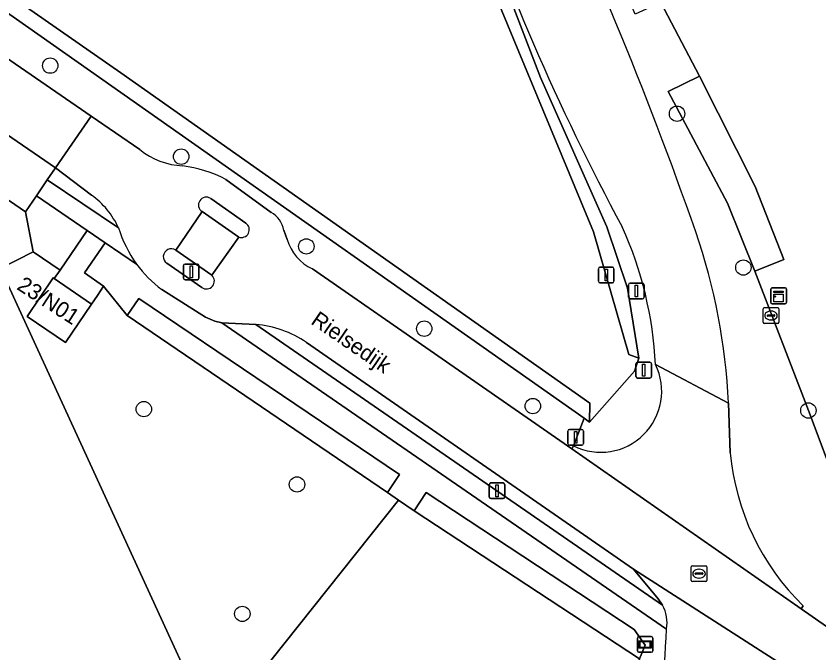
# Model space of a CAD drawing. Extents: x 163859 to 164644, y 379566 to 382155.
# Drawn here: x 164405.8 to 164456.9, y 381680.8 to 381721.3 of the extents above; entities that cross this region are included whole.
import ezdxf

# ---------------------------------------------------------------- set-up
doc = ezdxf.new("R2010")
doc.units = 0
for name, color, linetype in [('IMGEO_Afsluitpaal', 7, 'Continuous'), ('IMGEO_Boom', 7, 'Continuous'), ('IMGEO_Erf', 7, 'Continuous'), ('IMGEO_Groenvoorziening', 7, 'Continuous'), ('IMGEO_Haag', 7, 'Continuous'), ('IMGEO_Hek', 7, 'Continuous'), ('IMGEO_Kast', 7, 'Continuous'), ('IMGEO_Lichtmast', 7, 'Continuous'), ('IMGEO_Openbare_ruimte_label', 7, 'Continuous'), ('IMGEO_Pand', 7, 'Continuous'), ('IMGEO_Pand_nummerreeks', 7, 'Continuous'), ('IMGEO_Parkeervlak_open', 7, 'Continuous'), ('IMGEO_Rijbaan_lokaal_gesloten', 7, 'Continuous'), ('IMGEO_Rijbaan_lokaal_halfverhard', 7, 'Continuous'), ('IMGEO_Rijbaan_lokaal_open', 7, 'Continuous'), ('IMGEO_Rioolput', 7, 'Continuous'), ('IMGEO_Verkeersbordpaal', 7, 'Continuous'), ('IMGEO_Voetpad_open', 7, 'Continuous'), ('IMGEO_Waterloop', 7, 'Continuous'), ('IMGEO_Wegwijzer', 7, 'Continuous')]:
    doc.layers.add(name, color=color, linetype=linetype)

msp = doc.modelspace()

# ---------------------------------------------------------------- linework, layer by layer
at = {"layer": 'IMGEO_Afsluitpaal'}
for p, q in [((164444.797, 381703.434), (164444.797, 381704.234)), ((164444.797, 381704.234), (164444.797, 381703.434)), ((164444.897, 381704.334), (164445.687, 381704.334)), ((164445.687, 381704.334), (164444.897, 381704.334)), ((164445.787, 381704.234), (164445.787, 381703.434)), ((164445.787, 381703.434), (164445.787, 381704.234)), ((164445.687, 381703.334), (164444.897, 381703.334)), ((164444.897, 381703.334), (164445.687, 381703.334)), ((164445.274, 381698.398), (164445.274, 381699.198)), ((164445.274, 381699.198), (164445.274, 381698.398)), ((164445.374, 381699.298), (164446.164, 381699.298)), ((164446.164, 381699.298), (164445.374, 381699.298)), ((164446.264, 381699.198), (164446.264, 381698.398)), ((164446.264, 381698.398), (164446.264, 381699.198)), ((164446.164, 381698.298), (164445.374, 381698.298)), ((164445.374, 381698.298), (164446.164, 381698.298)), ((164440.936, 381694.125), (164440.936, 381694.925)), ((164440.936, 381694.925), (164440.936, 381694.125)), ((164441.036, 381695.025), (164441.826, 381695.025)), ((164441.826, 381695.025), (164441.036, 381695.025)), ((164441.926, 381694.925), (164441.926, 381694.125)), ((164441.926, 381694.125), (164441.926, 381694.925)), ((164441.826, 381694.025), (164441.036, 381694.025)), ((164441.036, 381694.025), (164441.826, 381694.025))]:
    msp.add_line(p, q, dxfattribs=at)
for points in [[(164445.217, 381704.209), (164445.367, 381704.209), (164445.367, 381703.459), (164445.217, 381703.459), (164445.217, 381704.209)], [(164445.694, 381699.173), (164445.844, 381699.173), (164445.844, 381698.423), (164445.694, 381698.423), (164445.694, 381699.173)], [(164441.356, 381694.9), (164441.506, 381694.9), (164441.506, 381694.15), (164441.356, 381694.15), (164441.356, 381694.9)]]:
    msp.add_lwpolyline(points, dxfattribs=at)
for centre, start, end in [((164444.897, 381704.234), 90, 180), ((164444.897, 381704.234), 90, 180), ((164445.687, 381704.234), 0, 90), ((164445.687, 381704.234), 360, 90), ((164444.897, 381703.434), 180, 270), ((164444.897, 381703.434), 180, 270), ((164445.687, 381703.434), 270, 0), ((164445.687, 381703.434), 270, 0), ((164445.374, 381699.198), 90, 180), ((164445.374, 381699.198), 90, 180), ((164446.164, 381699.198), 0, 90), ((164446.164, 381699.198), 360, 90), ((164445.374, 381698.398), 180, 270), ((164445.374, 381698.398), 180, 270), ((164446.164, 381698.398), 270, 0), ((164446.164, 381698.398), 270, 0), ((164441.036, 381694.925), 90, 180), ((164441.036, 381694.925), 90, 180), ((164441.826, 381694.925), 0, 90), ((164441.826, 381694.925), 360, 90), ((164441.036, 381694.125), 180, 270), ((164441.036, 381694.125), 180, 270), ((164441.826, 381694.125), 270, 0), ((164441.826, 381694.125), 270, 0)]:
    msp.add_arc(centre, 0.1, start, end, dxfattribs=at)
at = {"layer": 'IMGEO_Boom'}
for centre in [(164407.999, 381718.165), (164447.885, 381715.108), (164416.332, 381712.377), (164424.297, 381706.667), (164452.106, 381705.325), (164431.799, 381701.437), (164438.709, 381696.515), (164413.958, 381696.321), (164456.242, 381696.233), (164423.704, 381691.53), (164420.224, 381683.299)]:
    msp.add_circle(centre, 0.489, dxfattribs=at)
at = {"layer": 'IMGEO_Erf'}
for points in [[(164373.541, 381743.437), (164381.128, 381738.044), (164380.075, 381736.577), (164381.302, 381735.727), (164381.018, 381735.317), (164382.848, 381734.057), (164384.279, 381736.27), (164384.767, 381737.008), (164412.499, 381717.701), (164442.345, 381696.707), (164442.313, 381695.498), (164445.182, 381698.732), (164445.453, 381699.564), (164444.814, 381699.801), (164442.562, 381707.597), (164432.716, 381731.373), (164424.257, 381752.745), (164423.35, 381755.66), (164420.288, 381764.098), (164421.545, 381764.607), (164416.201, 381779.849)], [(164545.187, 381772.796), (164538.087, 381770.586), (164534.647, 381771.115), (164468.83, 381745.172), (164457.1, 381740.602), (164440.833, 381734.263), (164442.117, 381733.052), (164446.861, 381722.173), (164449.308, 381717.487), (164452.858, 381710.476), (164454.684, 381705.828), (164452.839, 381705.104), (164456.242, 381696.233), (164460.508, 381684.892), (164470.413, 381677.426)], [(164404.83, 381705.266), (164406.925, 381706.323), (164406.418, 381708.86), (164381.892, 381725.724), (164366.579, 381736.251)], [(164441.086, 381626.391), (164437.24, 381634.76), (164435.396, 381638.772), (164432.979, 381644.03), (164418.395, 381675.757), (164404.83, 381705.266)]]:
    msp.add_lwpolyline(points, dxfattribs=at)
at = {"layer": 'IMGEO_Groenvoorziening'}
for points in [[(164455.903, 381683.819), (164455.774, 381683.629), (164466.526, 381676.141), (164470.413, 381677.426), (164460.508, 381684.892), (164456.242, 381696.233), (164452.839, 381705.104), (164451.098, 381709.418), (164447.311, 381716.527), (164449.308, 381717.487), (164446.861, 381722.173), (164445.218, 381721.442), (164440.48, 381732.584), (164442.117, 381733.052), (164440.833, 381734.263), (164434.331, 381751.745), (164433.997, 381752.734), (164433.526, 381754.803), (164427.546, 381772.442), (164427.349, 381773.022), (164418.253, 381799.855)], [(164416.201, 381779.849), (164421.545, 381764.607), (164424.509, 381756.221), (164425.411, 381753.268), (164439.193, 381717.401), (164443.41, 381707.913), (164444.739, 381704.016), (164445.453, 381699.564), (164445.182, 381698.732), (164442.313, 381695.498), (164441.971, 381695.738), (164441.297, 381693.99)], [(164411.916, 381716.853), (164384.279, 381736.27), (164382.848, 381734.057), (164385.909, 381731.949), (164410.608, 381714.952), (164413.701, 381712.823)], [(164424.684, 381705.234), (164441.191, 381693.787), (164441.297, 381693.99), (164441.971, 381695.738), (164411.916, 381716.853)], [(164408.346, 381711.663), (164407.816, 381710.901)], [(164410.627, 381709.931), (164408.346, 381711.663)], [(164407.816, 381710.901), (164412.337, 381707.852)], [(164419.173, 381710.931), (164422.052, 381708.834)], [(164420.438, 381708.15), (164418.21, 381709.722)], [(164417.659, 381708.884), (164419.995, 381707.267)], [(164422.863, 381707.691), (164423.088, 381707.112)], [(164413.488, 381705.549), (164411.502, 381706.899), (164410.178, 381704.987), (164411.398, 381704.132), (164412.893, 381702.27), (164413.634, 381703.357), (164430.229, 381692.16), (164429.462, 381691.018), (164430.172, 381690.536), (164431.154, 381689.854), (164431.926, 381691.02), (164445.149, 381682.312), (164445.862, 381681.301), (164445.507, 381680.437), (164441.513, 381656.721), (164439.427, 381648.452), (164432.979, 381644.03), (164435.396, 381638.772), (164437.55, 381639.663), (164442.442, 381643.541)], [(164418.287, 381704.834), (164415.993, 381706.42)], [(164415.41, 381705.593), (164417.638, 381704.058)], [(164447.209, 381682.336), (164418.924, 381701.808), (164418.468, 381701.923), (164417.871, 381702.173), (164415.108, 381703.926)], [(164421.084, 381701.704), (164446.953, 381683.86), (164446.689, 381684.251), (164445.106, 381686.132), (164424.306, 381700.566)], [(164451.153, 381696.71), (164451.272, 381693.533)]]:
    msp.add_lwpolyline(points, dxfattribs=at)
for points in [[(164406.925, 381706.323), (164408.629, 381705.166), (164410.356, 381707.679), (164407.122, 381709.878), (164406.418, 381708.86)], [(164412.893, 381702.27), (164411.398, 381704.132), (164411.007, 381703.551), (164410.636, 381702.998), (164408.971, 381700.556), (164406.531, 381702.22), (164408.196, 381704.662), (164408.255, 381704.621), (164408.629, 381705.166), (164406.925, 381706.323), (164404.83, 381705.266), (164418.395, 381675.757), (164430.172, 381690.536), (164429.462, 381691.018)], [(164445.507, 381680.437), (164431.154, 381689.854), (164430.172, 381690.536), (164418.395, 381675.757), (164432.979, 381644.03), (164439.427, 381648.452), (164441.513, 381656.721)]]:
    msp.add_lwpolyline(points, close=True, dxfattribs=at)
for centre, radius, start, end in [((164221.983, 381628.478), 240.478, 19.20953, 25.99054), ((164576.493, 381779.107), 150.062, 198.44616, 208.32428), ((164416.629, 381716.454), 4.664, 231.1133, 267.4426), ((164415.29, 381703.367), 8.502, 62.8239, 82.3543), ((164407.619, 381705.714), 5.18, 24.3783, 54.497), ((164417.936, 381709.302), 0.501, 56.8492, 236.4995), ((164421.259, 381707.412), 1.628, 9.8569, 60.8573), ((164420.17, 381707.732), 0.497, 249.3569, 57.3574), ((164422.47, 381697.97), 24.074, 2.8147, 24.3816), ((164413.003, 381695.065), 38.185, 2.4692, 19.1656), ((164425.923, 381707.905), 2.944, 195.6158, 245.1027), ((164415.7, 381706.008), 0.506, 54.5679, 235.0676), ((164419.638, 381710.068), 7.632, 216.3064, 233.5876), ((164417.937, 381704.467), 0.507, 233.8282, 46.3576), ((164420.507, 381694.941), 6.788, 55.9678, 85.1261), ((164443.036, 381697.45), 3.873, 243.3112, 26.0706), ((164466.8, 381694.975), 15.595, 185.3051, 225.6724), ((164384.013, 381684.587), 63.236, 349.92525, 357.95994)]:
    msp.add_arc(centre, radius, start, end, dxfattribs=at)
at = {"layer": 'IMGEO_Haag'}
for points in [[(164408.346, 381711.663), (164407.816, 381710.901)], [(164410.627, 381709.931), (164408.346, 381711.663)], [(164407.816, 381710.901), (164412.337, 381707.852)], [(164420.438, 381708.15), (164418.21, 381709.722)], [(164417.659, 381708.884), (164419.995, 381707.267)], [(164418.287, 381704.834), (164415.993, 381706.42)], [(164415.41, 381705.593), (164417.638, 381704.058)], [(164421.084, 381701.704), (164446.953, 381683.86), (164446.689, 381684.251), (164445.106, 381686.132), (164424.306, 381700.566)]]:
    msp.add_lwpolyline(points, dxfattribs=at)
for centre, radius, start, end in [((164407.619, 381705.714), 5.18, 24.3783, 54.497), ((164417.936, 381709.302), 0.501, 56.8492, 236.4995), ((164420.17, 381707.732), 0.497, 249.3569, 57.3574), ((164415.7, 381706.008), 0.506, 54.5679, 235.0676), ((164417.937, 381704.467), 0.507, 233.8282, 46.3576), ((164420.507, 381694.941), 6.788, 55.9678, 85.1261)]:
    msp.add_arc(centre, radius, start, end, dxfattribs=at)
at = {"layer": 'IMGEO_Hek'}
for points in [[(164429.462, 381691.018), (164430.172, 381690.536)], [(164430.172, 381690.536), (164418.395, 381675.757)]]:
    msp.add_lwpolyline(points, dxfattribs=at)
at = {"layer": 'IMGEO_Kast'}
for p, q in [((164453.925, 381704.024), (164454.766, 381704.024)), ((164454.766, 381704.024), (164453.925, 381704.024)), ((164453.85, 381703.099), (164453.85, 381703.94)), ((164453.85, 381703.94), (164453.85, 381703.099)), ((164454.85, 381703.949), (164454.85, 381703.108)), ((164454.85, 381703.108), (164454.85, 381703.949)), ((164454.775, 381703.024), (164453.934, 381703.024)), ((164453.934, 381703.024), (164454.775, 381703.024))]:
    msp.add_line(p, q, dxfattribs=at)
for points in [[(164454.045, 381703.814), (164454.645, 381703.814), (164454.645, 381703.729), (164454.045, 381703.729), (164454.045, 381703.814)], [(164454.045, 381703.639), (164454.645, 381703.639), (164454.645, 381703.15), (164454.045, 381703.15), (164454.045, 381703.639)]]:
    msp.add_lwpolyline(points, dxfattribs=at)
msp.add_circle((164454.129, 381703.488), 0.0377, dxfattribs=at)
for centre, start, end in [((164453.928, 381703.946), 92.4484, 184.2845), ((164453.928, 381703.946), 92.4484, 184.2845), ((164454.772, 381703.946), 2.4484, 94.2845), ((164454.772, 381703.946), 2.4484, 94.2845), ((164453.928, 381703.102), 182.4484, 274.2845), ((164453.928, 381703.102), 182.4484, 274.2845), ((164454.772, 381703.102), 272.4484, 4.2845), ((164454.772, 381703.102), 272.4484, 4.2845)]:
    msp.add_arc(centre, 0.0779, start, end, dxfattribs=at)
at = {"layer": 'IMGEO_Lichtmast'}
for p, q in [((164416.477, 381704.649), (164416.477, 381705.449)), ((164416.477, 381705.449), (164416.477, 381704.649)), ((164416.577, 381705.549), (164417.367, 381705.549)), ((164417.367, 381705.549), (164416.577, 381705.549)), ((164417.467, 381705.449), (164417.467, 381704.649)), ((164417.467, 381704.649), (164417.467, 381705.449)), ((164417.367, 381704.549), (164416.577, 381704.549)), ((164416.577, 381704.549), (164417.367, 381704.549)), ((164435.935, 381690.728), (164435.935, 381691.528)), ((164435.935, 381691.528), (164435.935, 381690.728)), ((164436.035, 381691.628), (164436.825, 381691.628)), ((164436.825, 381691.628), (164436.035, 381691.628)), ((164436.925, 381691.528), (164436.925, 381690.728)), ((164436.925, 381690.728), (164436.925, 381691.528)), ((164436.825, 381690.628), (164436.035, 381690.628)), ((164436.035, 381690.628), (164436.825, 381690.628))]:
    msp.add_line(p, q, dxfattribs=at)
for points in [[(164416.897, 381705.424), (164417.047, 381705.424), (164417.047, 381704.674), (164416.897, 381704.674), (164416.897, 381705.424)], [(164436.355, 381691.503), (164436.505, 381691.503), (164436.505, 381690.753), (164436.355, 381690.753), (164436.355, 381691.503)]]:
    msp.add_lwpolyline(points, dxfattribs=at)
for centre, start, end in [((164416.577, 381705.449), 90, 180), ((164416.577, 381705.449), 90, 180), ((164417.367, 381705.449), 0, 90), ((164417.367, 381705.449), 360, 90), ((164416.577, 381704.649), 180, 270), ((164416.577, 381704.649), 180, 270), ((164417.367, 381704.649), 270, 0), ((164417.367, 381704.649), 270, 0), ((164436.035, 381691.528), 90, 180), ((164436.035, 381691.528), 90, 180), ((164436.825, 381691.528), 0, 90), ((164436.825, 381691.528), 360, 90), ((164436.035, 381690.728), 180, 270), ((164436.035, 381690.728), 180, 270), ((164436.825, 381690.728), 270, 0), ((164436.825, 381690.728), 270, 0)]:
    msp.add_arc(centre, 0.1, start, end, dxfattribs=at)
at = {"layer": 'IMGEO_Pand'}
msp.add_lwpolyline([(164408.255, 381704.621), (164408.196, 381704.662), (164406.531, 381702.22), (164408.971, 381700.556), (164410.636, 381702.998)], close=True, dxfattribs=at)
at = {"layer": 'IMGEO_Parkeervlak_open'}
msp.add_lwpolyline([(164352.536, 381750), (164324.768, 381769.068), (164324.32, 381768.391), (164323.62, 381767.407), (164322.896, 381766.247), (164346.556, 381750), (164366.579, 381736.251), (164381.892, 381725.724), (164406.418, 381708.86), (164407.122, 381709.878), (164407.816, 381710.901), (164408.346, 381711.663), (164383.72, 381728.586)], close=True, dxfattribs=at)
at = {"layer": 'IMGEO_Rijbaan_lokaal_gesloten'}
for points in [[(164322.955, 381770.199), (164324.768, 381769.068), (164352.536, 381750), (164383.72, 381728.586), (164408.346, 381711.663), (164410.608, 381714.952), (164385.909, 381731.949), (164382.848, 381734.057), (164381.018, 381735.317), (164360.792, 381749.337), (164360.25, 381749.708), (164359.822, 381750), (164324.169, 381774.363)], [(164413.701, 381712.823), (164410.608, 381714.952), (164408.346, 381711.663), (164410.627, 381709.931)], [(164422.052, 381708.834), (164419.173, 381710.931)], [(164418.21, 381709.722), (164420.438, 381708.15)], [(164415.993, 381706.42), (164417.659, 381708.884)], [(164423.088, 381707.112), (164422.863, 381707.691)], [(164419.995, 381707.267), (164418.287, 381704.834)], [(164417.638, 381704.058), (164415.41, 381705.593)], [(164503.048, 381650.429), (164500, 381652.587), (164485.583, 381662.794), (164479.098, 381667.385), (164474.908, 381670.303), (164466.526, 381676.141), (164455.774, 381683.629), (164441.191, 381693.787), (164424.684, 381705.234)], [(164415.108, 381703.926), (164417.871, 381702.173), (164418.468, 381701.923), (164418.924, 381701.808), (164421.084, 381701.704)], [(164424.306, 381700.566), (164445.106, 381686.132), (164456.317, 381678.951), (164476.958, 381664.61), (164500, 381648.336), (164501.109, 381647.553)], [(164453.434, 381678.671), (164455.059, 381679.039), (164456.317, 381678.951), (164445.106, 381686.132), (164446.689, 381684.251), (164446.953, 381683.86)]]:
    msp.add_lwpolyline(points, dxfattribs=at)
for centre, radius, start, end in [((164416.629, 381716.454), 4.664, 231.1133, 267.4426), ((164415.29, 381703.367), 8.502, 62.8239, 82.3543), ((164407.619, 381705.714), 5.18, 24.3783, 54.497), ((164417.936, 381709.302), 0.501, 56.8492, 236.4995), ((164421.259, 381707.412), 1.628, 9.8569, 60.8573), ((164420.17, 381707.732), 0.497, 249.3569, 57.3574), ((164420.524, 381710.505), 8.606, 197.9525, 215.1576), ((164425.923, 381707.905), 2.944, 195.6158, 245.1027), ((164415.7, 381706.008), 0.506, 54.5679, 235.0676), ((164419.638, 381710.068), 7.632, 216.3064, 233.5876), ((164417.937, 381704.467), 0.507, 233.8282, 46.3576), ((164420.507, 381694.941), 6.788, 55.9678, 85.1261), ((164445.046, 381682.756), 2.204, 349.0095, 30.0614), ((164384.013, 381684.587), 63.236, 349.92525, 357.95994)]:
    msp.add_arc(centre, radius, start, end, dxfattribs=at)
at = {"layer": 'IMGEO_Rijbaan_lokaal_halfverhard'}
msp.add_lwpolyline([(164446.515, 381699.152), (164451.153, 381696.71)], dxfattribs=at)
for centre, radius, start, end in [((164221.983, 381628.478), 240.478, 19.20953, 25.99054), ((164576.493, 381779.107), 150.062, 198.44616, 208.32428), ((164422.47, 381697.97), 24.074, 2.8147, 24.3816), ((164413.003, 381695.065), 38.185, 2.4692, 19.1656)]:
    msp.add_arc(centre, radius, start, end, dxfattribs=at)
at = {"layer": 'IMGEO_Rijbaan_lokaal_open'}
msp.add_lwpolyline([(164419.995, 381707.267), (164417.659, 381708.884), (164415.993, 381706.42), (164418.287, 381704.834)], close=True, dxfattribs=at)
for points in [[(164451.272, 381693.533), (164451.153, 381696.71), (164446.515, 381699.152)], [(164441.297, 381693.99), (164441.191, 381693.787), (164455.774, 381683.629), (164455.903, 381683.819)]]:
    msp.add_lwpolyline(points, dxfattribs=at)
for centre, radius, start, end in [((164443.036, 381697.45), 3.873, 243.3112, 26.0706), ((164466.8, 381694.975), 15.595, 185.3051, 225.6724)]:
    msp.add_arc(centre, radius, start, end, dxfattribs=at)
at = {"layer": 'IMGEO_Rioolput'}
for p, q in [((164453.363, 381701.847), (164453.363, 381702.699)), ((164453.438, 381702.773), (164454.29, 381702.773)), ((164453.851, 381702.553), (164453.876, 381702.553)), ((164454.364, 381702.699), (164454.364, 381701.847)), ((164453.622, 381702.267), (164453.622, 381702.279)), ((164454.06, 381702.23), (164453.662, 381702.23)), ((164453.665, 381702.316), (164454.063, 381702.316)), ((164453.874, 381701.993), (164453.849, 381701.993)), ((164454.106, 381702.279), (164454.106, 381702.267)), ((164454.29, 381701.773), (164453.438, 381701.773)), ((164448.785, 381685.432), (164448.785, 381686.284)), ((164448.86, 381686.358), (164449.712, 381686.358)), ((164449.786, 381686.284), (164449.786, 381685.432)), ((164449.044, 381685.852), (164449.044, 381685.864)), ((164449.482, 381685.815), (164449.084, 381685.815)), ((164449.087, 381685.901), (164449.485, 381685.901)), ((164449.273, 381686.138), (164449.298, 381686.138)), ((164449.528, 381685.864), (164449.528, 381685.852)), ((164449.712, 381685.358), (164448.86, 381685.358)), ((164449.296, 381685.578), (164449.271, 381685.578))]:
    msp.add_line(p, q, dxfattribs=at)
for points in [[(164453.363, 381701.847), (164453.363, 381702.699)], [(164453.438, 381702.773), (164454.29, 381702.773)], [(164454.364, 381702.699), (164454.364, 381701.847)], [(164454.29, 381701.773), (164453.438, 381701.773)], [(164448.785, 381685.432), (164448.785, 381686.284)], [(164448.86, 381686.358), (164449.712, 381686.358)], [(164449.786, 381686.284), (164449.786, 381685.432)], [(164449.712, 381685.358), (164448.86, 381685.358)]]:
    msp.add_lwpolyline(points, dxfattribs=at)
for centre, radius, start, end in [((164453.44, 381702.697), 0.0765, 91.552, 178.448), ((164453.44, 381702.697), 0.0765, 91.552, 178.448), ((164454.288, 381702.697), 0.0765, 1.552, 88.448), ((164454.288, 381702.697), 0.0765, 1.552, 88.448), ((164453.662, 381702.276), 0.0403, 85.8775, 175.7526), ((164453.659, 381702.266), 0.0366, 178.938, 274.7102), ((164454.063, 381702.273), 0.043, 264.8664, 352.4533), ((164454.067, 381702.278), 0.0386, 1.7309, 96.639), ((164453.44, 381701.849), 0.0765, 181.552, 268.448), ((164453.44, 381701.849), 0.0765, 181.552, 268.448), ((164454.288, 381701.849), 0.0765, 271.552, 358.448), ((164454.288, 381701.849), 0.0765, 271.552, 358.448), ((164448.862, 381686.282), 0.0765, 91.552, 178.448), ((164448.862, 381686.282), 0.0765, 91.552, 178.448), ((164449.71, 381686.282), 0.0765, 1.552, 88.448), ((164449.71, 381686.282), 0.0765, 1.552, 88.448), ((164449.084, 381685.861), 0.0403, 85.8775, 175.7526), ((164449.081, 381685.851), 0.0366, 178.938, 274.7102), ((164449.485, 381685.858), 0.043, 264.8664, 352.4533), ((164449.489, 381685.863), 0.0386, 1.7309, 96.639), ((164448.862, 381685.434), 0.0765, 181.552, 268.448), ((164448.862, 381685.434), 0.0765, 181.552, 268.448), ((164449.71, 381685.434), 0.0765, 271.552, 358.448), ((164449.71, 381685.434), 0.0765, 271.552, 358.448)]:
    msp.add_arc(centre, radius, start, end, dxfattribs=at)
for centre, major_axis, ratio, start_param, end_param in [((164453.85, 381702.273), (-0.387, 0.002), 0.722429, 4.712389, 7.853982), ((164453.875, 381702.273), (-0.39, 0.002), 0.717154, 1.570796, 4.712389), ((164449.272, 381685.858), (-0.387, 0.002), 0.722429, 4.712389, 7.853982), ((164449.297, 381685.858), (-0.39, 0.002), 0.717154, 1.570796, 4.712389)]:
    msp.add_ellipse(centre, major_axis=major_axis, ratio=ratio, start_param=start_param, end_param=end_param, dxfattribs=at)
at = {"layer": 'IMGEO_Verkeersbordpaal'}
for p, q in [((164442.883, 381704.448), (164442.883, 381705.248)), ((164442.883, 381705.248), (164442.883, 381704.448)), ((164442.983, 381705.348), (164443.773, 381705.348)), ((164443.773, 381705.348), (164442.983, 381705.348)), ((164443.873, 381705.248), (164443.873, 381704.448)), ((164443.873, 381704.448), (164443.873, 381705.248)), ((164443.773, 381704.348), (164442.983, 381704.348)), ((164442.983, 381704.348), (164443.773, 381704.348))]:
    msp.add_line(p, q, dxfattribs=at)
msp.add_lwpolyline([(164443.303, 381705.223), (164443.453, 381705.223), (164443.453, 381704.473), (164443.303, 381704.473), (164443.303, 381705.223)], dxfattribs=at)
for centre, start, end in [((164442.983, 381705.248), 90, 180), ((164442.983, 381705.248), 90, 180), ((164443.773, 381705.248), 0, 90), ((164443.773, 381705.248), 360, 90), ((164442.983, 381704.448), 180, 270), ((164442.983, 381704.448), 180, 270), ((164443.773, 381704.448), 270, 0), ((164443.773, 381704.448), 270, 0)]:
    msp.add_arc(centre, 0.1, start, end, dxfattribs=at)
at = {"layer": 'IMGEO_Voetpad_open'}
for points in [[(164412.337, 381707.852), (164407.816, 381710.901), (164407.122, 381709.878), (164410.356, 381707.679), (164411.502, 381706.899), (164413.488, 381705.549)], [(164446.953, 381683.86), (164421.084, 381701.704), (164418.924, 381701.808), (164447.209, 381682.336)]]:
    msp.add_lwpolyline(points, dxfattribs=at)
msp.add_lwpolyline([(164410.356, 381707.679), (164408.629, 381705.166), (164408.255, 381704.621), (164410.636, 381702.998), (164411.007, 381703.551), (164411.398, 381704.132), (164410.178, 381704.987), (164411.502, 381706.899)], close=True, dxfattribs=at)
for centre, radius, start, end in [((164420.524, 381710.505), 8.606, 197.9525, 215.1576), ((164445.046, 381682.756), 2.204, 349.0095, 30.0614)]:
    msp.add_arc(centre, radius, start, end, dxfattribs=at)
at = {"layer": 'IMGEO_Waterloop'}
for points in [[(164444.739, 381704.016), (164443.41, 381707.913), (164439.193, 381717.401), (164425.411, 381753.268), (164424.509, 381756.221), (164421.545, 381764.607), (164420.288, 381764.098), (164423.35, 381755.66), (164424.257, 381752.745), (164432.716, 381731.373), (164442.562, 381707.597), (164444.814, 381699.801), (164445.453, 381699.564)], [(164412.499, 381717.701), (164384.767, 381737.008), (164384.279, 381736.27), (164411.916, 381716.853), (164441.971, 381695.738), (164442.313, 381695.498), (164442.345, 381696.707)], [(164454.684, 381705.828), (164452.858, 381710.476), (164449.308, 381717.487), (164447.311, 381716.527), (164451.098, 381709.418), (164452.839, 381705.104)], [(164430.229, 381692.16), (164413.634, 381703.357), (164412.893, 381702.27), (164429.462, 381691.018)], [(164445.862, 381681.301), (164445.149, 381682.312), (164431.926, 381691.02), (164431.154, 381689.854), (164445.507, 381680.437)]]:
    msp.add_lwpolyline(points, close=True, dxfattribs=at)
at = {"layer": 'IMGEO_Wegwijzer'}
for p, q in [((164445.36, 381680.954), (164445.36, 381681.754)), ((164445.36, 381681.754), (164445.36, 381680.954)), ((164445.46, 381681.854), (164446.25, 381681.854)), ((164446.25, 381681.854), (164445.46, 381681.854)), ((164446.35, 381681.754), (164446.35, 381680.954)), ((164446.35, 381680.954), (164446.35, 381681.754)), ((164446.25, 381680.854), (164445.46, 381680.854)), ((164445.46, 381680.854), (164446.25, 381680.854))]:
    msp.add_line(p, q, dxfattribs=at)
for points in [[(164445.461, 381681.586), (164446.249, 381681.586), (164446.249, 381681.122), (164445.461, 381681.122), (164445.461, 381681.586)], [(164445.526, 381681.521), (164445.526, 381681.187), (164446.184, 381681.187), (164446.184, 381681.521), (164445.526, 381681.521)]]:
    msp.add_lwpolyline(points, dxfattribs=at)
for centre, start, end in [((164445.46, 381681.754), 90, 180), ((164445.46, 381681.754), 90, 180), ((164446.25, 381681.754), 0, 90), ((164446.25, 381681.754), 360, 90), ((164445.46, 381680.954), 180, 270), ((164445.46, 381680.954), 180, 270), ((164446.25, 381680.954), 270, 0), ((164446.25, 381680.954), 270, 0)]:
    msp.add_arc(centre, 0.1, start, end, dxfattribs=at)

# ---------------------------------------------------------------- texts
at = {"layer": 'IMGEO_Openbare_ruimte_label'}
msp.add_text('Rielsedijk', height=1, rotation=325.5948, dxfattribs=at).set_placement((164424.523, 381701.784))
at = {"layer": 'IMGEO_Pand_nummerreeks'}
msp.add_text('23/N01', height=1, rotation=327.0296, dxfattribs=at).set_placement((164405.813, 381703.982))

doc.saveas('drawing.dxf')
